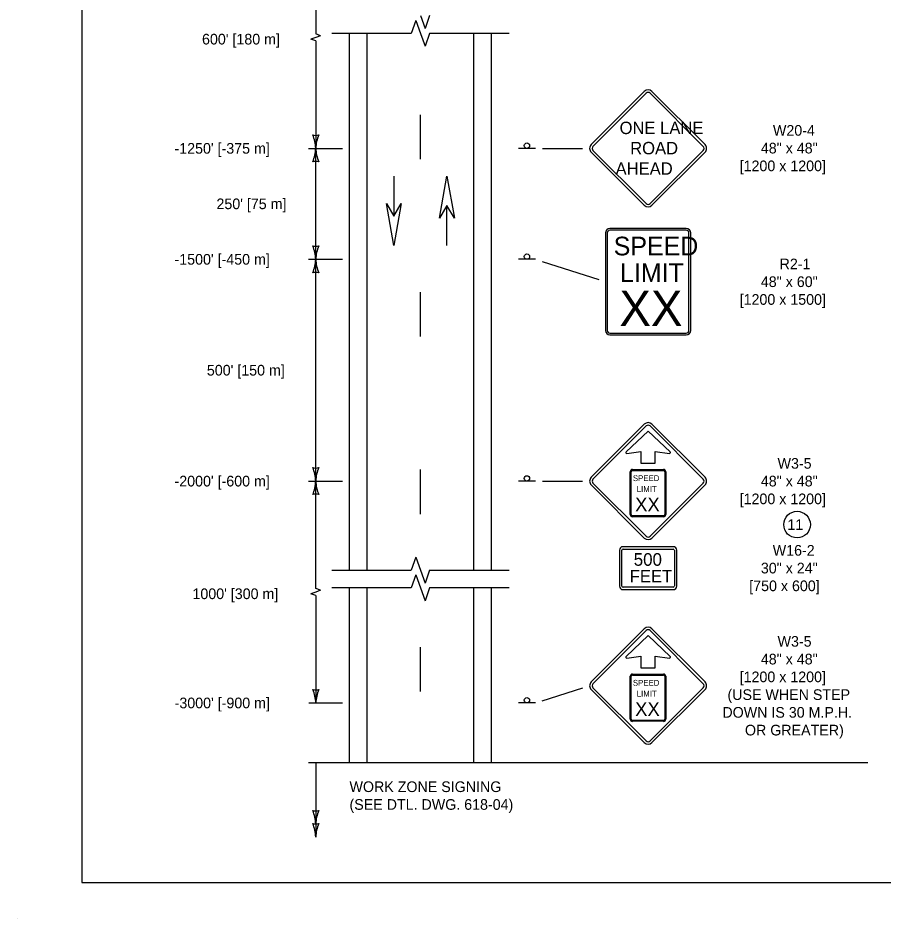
# Model space of a CAD drawing. Extents: x 49991.4 to 50021, y 49987.6 to 50011.4.
# Drawn here: x 49999.98 to 50004.85, y 49999.86 to 50004.93 of the extents above; entities that cross this region are included whole.
import ezdxf

# ---------------------------------------------------------------- set-up
doc = ezdxf.new("R2010")
doc.units = 0
for name, color, linetype in [('Level 1', 7, 'Continuous'), ('Level 2', 7, 'Continuous'), ('Level 3', 7, 'Continuous'), ('Level 6', 7, 'Continuous')]:
    doc.layers.add(name, color=color, linetype=linetype)

msp = doc.modelspace()

# ---------------------------------------------------------------- linework, layer by layer
at = {"layer": 'Level 1'}
for p, q in [((50001.8443, 50001.8221), (50001.8443, 50004.8471)), ((50001.9443, 50004.8119), (50001.9443, 50004.8482)), ((50001.9443, 50001.8221), (50001.9443, 50004.8471)), ((50002.5443, 50001.8221), (50002.5443, 50004.8471)), ((50002.6443, 50001.8221), (50002.6443, 50004.8471)), ((50003.5058, 50004.5198), (50003.2064, 50004.2205)), ((50003.5058, 50004.5198), (50003.5058, 50004.5198)), ((50003.848, 50004.2205), (50003.5486, 50004.5198)), ((50003.5159, 50004.5098), (50003.2165, 50004.2104)), ((50003.5159, 50004.5098), (50003.5159, 50004.5098)), ((50003.8379, 50004.2104), (50003.5385, 50004.5098)), ((50002.2443, 50004.1388), (50002.2443, 50004.3888)), ((50002.8923, 50004.1991), (50002.7963, 50004.1991)), ((50003.2064, 50004.1777), (50003.5058, 50003.8783)), ((50003.2165, 50004.1878), (50003.5159, 50003.8884)), ((50003.5385, 50003.8884), (50003.8379, 50004.1878)), ((50003.5486, 50003.8783), (50003.848, 50004.1777)), ((50002.094, 50004.0422), (50002.094, 50003.8163)), ((50002.0943, 50004.0422), (50002.0943, 50003.8163)), ((50002.3937, 50003.652), (50002.3937, 50003.8779)), ((50002.394, 50003.652), (50002.394, 50003.8779)), ((50003.2872, 50003.7227), (50003.2872, 50003.1727)), ((50003.2972, 50003.7227), (50003.2972, 50003.1727)), ((50003.7422, 50003.7477), (50003.3122, 50003.7477)), ((50003.7422, 50003.7377), (50003.3122, 50003.7377)), ((50003.7572, 50003.1727), (50003.7572, 50003.7227)), ((50003.7672, 50003.1727), (50003.7672, 50003.7227)), ((50002.8926, 50003.5738), (50002.7966, 50003.5738)), ((50002.2443, 50003.1388), (50002.2443, 50003.3888)), ((50003.3122, 50003.1577), (50003.7422, 50003.1577)), ((50003.3122, 50003.1477), (50003.7422, 50003.1477)), ((50003.5058, 50002.6448), (50003.2065, 50002.3455)), ((50003.5058, 50002.6448), (50003.5058, 50002.6448)), ((50003.8479, 50002.3455), (50003.5486, 50002.6448)), ((50003.5159, 50002.6347), (50003.2166, 50002.3354)), ((50003.5272, 50002.6063), (50003.4028, 50002.489)), ((50003.5159, 50002.6347), (50003.5159, 50002.6347)), ((50003.6516, 50002.489), (50003.5272, 50002.6063)), ((50003.8378, 50002.3354), (50003.5385, 50002.6347)), ((50003.4069, 50002.4804), (50003.4869, 50002.4904)), ((50003.4869, 50002.4904), (50003.4869, 50002.4249)), ((50003.5675, 50002.4249), (50003.5675, 50002.4904)), ((50003.5675, 50002.4904), (50003.6475, 50002.4804)), ((50003.4393, 50002.3898), (50003.6141, 50002.3898)), ((50003.4869, 50002.4249), (50003.5675, 50002.4249)), ((50003.5267, 50002.3898), (50003.5267, 50002.3898)), ((50002.2443, 50002.1388), (50002.2443, 50002.3888)), ((50003.4268, 50002.136), (50003.4268, 50002.3773)), ((50003.432, 50002.136), (50003.432, 50002.3773)), ((50003.4393, 50002.3846), (50003.6141, 50002.3846)), ((50003.6213, 50002.3773), (50003.6213, 50002.136)), ((50003.6265, 50002.3773), (50003.6265, 50002.136)), ((50002.8923, 50002.3241), (50002.7963, 50002.3241)), ((50003.2065, 50002.3027), (50003.5058, 50002.0034)), ((50003.2166, 50002.3128), (50003.5159, 50002.0135)), ((50003.5385, 50002.0135), (50003.8378, 50002.3128)), ((50003.5486, 50002.0034), (50003.8479, 50002.3027)), ((50003.6141, 50002.1288), (50003.4393, 50002.1288)), ((50003.6141, 50002.1236), (50003.4393, 50002.1236)), ((50003.3659, 50001.9344), (50003.3659, 50001.7328)), ((50003.3794, 50001.7328), (50003.3794, 50001.9344)), ((50003.6683, 50001.9546), (50003.3861, 50001.9546)), ((50003.3861, 50001.9411), (50003.6683, 50001.9411)), ((50003.6751, 50001.9344), (50003.6751, 50001.7328)), ((50003.6885, 50001.7328), (50003.6885, 50001.9344)), ((50001.8443, 50000.7385), (50001.8443, 50001.7221)), ((50001.9443, 50000.7385), (50001.9443, 50001.7221)), ((50002.5443, 50000.7385), (50002.5443, 50001.7221)), ((50002.6443, 50000.7385), (50002.6443, 50001.7221)), ((50003.6683, 50001.7261), (50003.3861, 50001.7261)), ((50003.3861, 50001.7126), (50003.6683, 50001.7126)), ((50003.5058, 50001.4918), (50003.2065, 50001.1925)), ((50003.5159, 50001.4817), (50003.2166, 50001.1824)), ((50003.5058, 50001.4918), (50003.5058, 50001.4918)), ((50003.5159, 50001.4817), (50003.5159, 50001.4817)), ((50003.8378, 50001.1824), (50003.5385, 50001.4817)), ((50003.8479, 50001.1925), (50003.5486, 50001.4918)), ((50003.5272, 50001.4533), (50003.4028, 50001.336)), ((50003.6516, 50001.336), (50003.5272, 50001.4533)), ((50002.2443, 50001.1388), (50002.2443, 50001.3888)), ((50003.4069, 50001.3274), (50003.4869, 50001.3374)), ((50003.4869, 50001.3374), (50003.4869, 50001.2719)), ((50003.5675, 50001.2719), (50003.5675, 50001.3374)), ((50003.5675, 50001.3374), (50003.6475, 50001.3274)), ((50003.4268, 50000.983), (50003.4268, 50001.2243)), ((50003.432, 50000.983), (50003.432, 50001.2243)), ((50003.4393, 50001.2368), (50003.6141, 50001.2368)), ((50003.4393, 50001.2316), (50003.6141, 50001.2316)), ((50003.4869, 50001.2719), (50003.5675, 50001.2719)), ((50003.5267, 50001.2368), (50003.5267, 50001.2368)), ((50003.6213, 50001.2243), (50003.6213, 50000.983)), ((50003.6265, 50001.2243), (50003.6265, 50000.983)), ((50003.2065, 50001.1497), (50003.5058, 50000.8504)), ((50003.2166, 50001.1598), (50003.5159, 50000.8605)), ((50003.5385, 50000.8605), (50003.8378, 50001.1598)), ((50003.5486, 50000.8504), (50003.8479, 50001.1497)), ((50002.8923, 50001.0741), (50002.7963, 50001.0741)), ((50003.6141, 50000.9758), (50003.4393, 50000.9758)), ((50003.6141, 50000.9706), (50003.4393, 50000.9706)), ((49999.9766, 49999.8624), (49999.9766, 49999.8624))]:
    msp.add_line(p, q, dxfattribs=at)
for points in [[(50008.6146, 50011.2628), (50000.3356, 50011.2628), (50000.3356, 50000.0624), (50008.6146, 50000.0624)], [(50002.352, 50003.8056), (50002.3937, 50004.0421), (50002.4356, 50003.8056), (50002.3937, 50003.8778)], [(50002.136, 50003.8886), (50002.0943, 50003.6521), (50002.0524, 50003.8886), (50002.0943, 50003.8164)]]:
    msp.add_lwpolyline(points, close=True, dxfattribs=at)
for centre in [(50002.8443, 50004.2144), (50002.8446, 50003.5891), (50002.8443, 50002.3394), (50002.8443, 50001.0893)]:
    msp.add_circle(centre, 0.0152, dxfattribs=at)
for centre, radius, start, end in [((50003.5272, 50004.4985), 0.0302, 45.0001, 134.9999), ((50003.5272, 50004.4985), 0.016, 45.0001, 134.9999), ((50003.2278, 50004.1991), 0.0302, 134.9999, 225.0001), ((50003.8266, 50004.1991), 0.0302, 314.9999, 45.0001), ((50003.2278, 50004.1991), 0.016, 134.9999, 225.0001), ((50003.8266, 50004.1991), 0.016, 314.9999, 45.0001), ((50003.5272, 50003.8997), 0.0302, 225.0001, 314.9999), ((50003.5272, 50003.8997), 0.016, 225.0001, 314.9999), ((50003.3122, 50003.7227), 0.025, 90, 180), ((50003.3122, 50003.7227), 0.015, 90, 180), ((50003.7422, 50003.7227), 0.025, 0, 90), ((50003.7422, 50003.7227), 0.015, 0, 90), ((50003.3122, 50003.1727), 0.025, 180, 270), ((50003.3122, 50003.1727), 0.015, 180, 270), ((50003.7422, 50003.1727), 0.025, 270, 0), ((50003.7422, 50003.1727), 0.015, 270, 0), ((50003.5272, 50002.6234), 0.0302, 45.0001, 134.9999), ((50003.5272, 50002.6234), 0.016, 45.0001, 134.9999), ((50003.4063, 50002.4854), 0.00508, 134.6287, 275.8295), ((50003.648, 50002.4854), 0.00509, 264.3826, 45.1649), ((50003.4393, 50002.3773), 0.0125, 90, 180), ((50003.6141, 50002.3773), 0.0125, 360, 90), ((50003.2279, 50002.3241), 0.0302, 134.9999, 225.0001), ((50003.4393, 50002.3773), 0.00728, 90, 180), ((50003.6141, 50002.3773), 0.00728, 360, 90), ((50003.8265, 50002.3241), 0.0302, 314.9999, 45.0001), ((50003.2279, 50002.3241), 0.016, 134.9999, 225.0001), ((50003.8265, 50002.3241), 0.016, 314.9999, 45.0001), ((50003.4393, 50002.136), 0.0125, 180, 270), ((50003.4393, 50002.136), 0.00728, 180, 270), ((50003.6141, 50002.136), 0.00728, 270, 360), ((50003.6141, 50002.136), 0.0125, 270, 360), ((50003.5272, 50002.0248), 0.0302, 225.0001, 314.9999), ((50003.5272, 50002.0248), 0.016, 225.0001, 314.9999), ((50003.3861, 50001.9344), 0.0202, 90, 180), ((50003.3861, 50001.9344), 0.00672, 90, 180), ((50003.6683, 50001.9344), 0.0202, 0, 90), ((50003.6683, 50001.9344), 0.00672, 0, 90), ((50003.3861, 50001.7328), 0.0202, 180, 270), ((50003.3861, 50001.7328), 0.00672, 180, 270), ((50003.6683, 50001.7328), 0.00672, 270, 360), ((50003.6683, 50001.7328), 0.0202, 270, 360), ((50003.5272, 50001.4704), 0.0302, 45.0001, 134.9999), ((50003.5272, 50001.4704), 0.016, 45.0001, 134.9999), ((50003.4063, 50001.3324), 0.00508, 134.6287, 275.8295), ((50003.648, 50001.3324), 0.00509, 264.3826, 45.1649), ((50003.4393, 50001.2243), 0.0125, 90, 180), ((50003.4393, 50001.2243), 0.00728, 90, 180), ((50003.6141, 50001.2243), 0.0125, 360, 90), ((50003.6141, 50001.2243), 0.00728, 360, 90), ((50003.2279, 50001.1711), 0.0302, 134.9999, 225.0001), ((50003.2279, 50001.1711), 0.016, 134.9999, 225.0001), ((50003.8265, 50001.1711), 0.016, 314.9999, 45.0001), ((50003.8265, 50001.1711), 0.0302, 314.9999, 45.0001), ((50003.4393, 50000.983), 0.0125, 180, 270), ((50003.4393, 50000.983), 0.00728, 180, 270), ((50003.6141, 50000.983), 0.00728, 270, 360), ((50003.6141, 50000.983), 0.0125, 270, 360), ((50003.5272, 50000.8718), 0.0302, 225.0001, 314.9999), ((50003.5272, 50000.8718), 0.016, 225.0001, 314.9999)]:
    msp.add_arc(centre, radius, start, end, dxfattribs=at)
at = {"layer": 'Level 2'}
msp.add_circle((50004.3665, 50002.0791), 0.075, dxfattribs=at)
at = {"layer": 'Level 3'}
for p, q in [((50001.6543, 50005.3709), (50001.6544, 50004.8435)), ((50001.6544, 50004.8241), (50001.627, 50004.8144)), ((50001.6818, 50004.8338), (50001.6544, 50004.8435)), ((50001.6818, 50004.8338), (50001.6544, 50004.8241)), ((50001.6541, 50004.8048), (50001.627, 50004.8144)), ((50001.6541, 50004.8048), (50001.6544, 50004.1991)), ((50001.6143, 50004.1991), (50001.8043, 50004.1991)), ((50001.6544, 50003.5738), (50001.6544, 50004.1991)), ((50002.9323, 50004.1991), (50003.1576, 50004.1991)), ((50001.6144, 50003.5738), (50001.8043, 50003.5738)), ((50001.6544, 50002.3241), (50001.6544, 50003.5738)), ((50002.9307, 50003.5616), (50003.2491, 50003.4599)), ((50001.6144, 50002.3241), (50001.8043, 50002.3241)), ((50001.6544, 50001.7185), (50001.6544, 50002.3241)), ((50002.9323, 50002.3241), (50003.1577, 50002.3241)), ((50001.6544, 50001.6991), (50001.627, 50001.6894)), ((50001.655, 50001.6795), (50001.627, 50001.6894)), ((50001.6818, 50001.7088), (50001.6544, 50001.7185)), ((50001.6818, 50001.7088), (50001.6544, 50001.6991)), ((50001.655, 50001.6795), (50001.655, 50001.0741)), ((50002.9304, 50001.0862), (50003.1595, 50001.159)), ((50001.615, 50001.0741), (50001.8043, 50001.0741)), ((50001.6143, 50000.7385), (50004.7645, 50000.7385)), ((50001.6544, 50000.7385), (50001.6544, 50000.3188))]:
    msp.add_line(p, q, dxfattribs=at)
for centre, radius, start, end in [((50001.6544, 50004.3273), 0.0548, 252.1388, 287.8612), ((50001.4217, 50004.1876), 0.233, 2.8273, 22.0772), ((50001.8765, 50004.1899), 0.2223, 157.456, 177.6395), ((50001.4323, 50004.2082), 0.2223, 337.456, 357.6395), ((50001.8871, 50004.2106), 0.233, 182.8273, 202.0772), ((50001.6544, 50004.0709), 0.0548, 72.1388, 107.8612), ((50001.6544, 50003.702), 0.0548, 252.1388, 287.8612), ((50001.4217, 50003.5623), 0.233, 2.8273, 22.0772), ((50001.8765, 50003.5647), 0.2223, 157.456, 177.6395), ((50001.4323, 50003.583), 0.2223, 337.456, 357.6395), ((50001.8871, 50003.5853), 0.233, 182.8273, 202.0772), ((50001.6544, 50003.4456), 0.0548, 72.1388, 107.8612), ((50001.6544, 50002.4523), 0.0548, 252.1388, 287.8612), ((50001.4217, 50002.3126), 0.233, 2.8273, 22.0772), ((50001.8765, 50002.3149), 0.2223, 157.456, 177.6395), ((50001.4323, 50002.3332), 0.2223, 337.456, 357.6395), ((50001.8871, 50002.3356), 0.233, 182.8273, 202.0772), ((50001.6544, 50002.1959), 0.0548, 72.1388, 107.8612), ((50001.655, 50001.2023), 0.0548, 252.1388, 287.8612), ((50001.4223, 50001.0626), 0.233, 2.8273, 22.0772), ((50001.8771, 50001.0649), 0.2223, 157.456, 177.6395), ((50001.6544, 50000.5205), 0.0548, 252.1388, 287.8612), ((50001.4217, 50000.3807), 0.233, 2.8273, 22.0772), ((50001.8765, 50000.3831), 0.2223, 157.456, 177.6395), ((50001.6544, 50000.447), 0.0548, 252.1388, 287.8612), ((50001.4217, 50000.3073), 0.233, 2.8273, 22.0772), ((50001.8765, 50000.3096), 0.2223, 157.456, 177.6395)]:
    msp.add_arc(centre, radius, start, end, dxfattribs=at)
at = {"layer": 'Level 6'}
for p, q in [((50002.2443, 50004.9471), (50002.2702, 50004.874)), ((50002.2961, 50004.9471), (50002.2702, 50004.874)), ((50002.2184, 50004.9202), (50002.1925, 50004.8471)), ((50002.2184, 50004.9202), (50002.2443, 50004.8471)), ((50002.1925, 50004.8471), (50001.7443, 50004.8471)), ((50002.2443, 50004.8471), (50002.2702, 50004.774)), ((50002.2961, 50004.8471), (50002.2702, 50004.774)), ((50002.7443, 50004.8471), (50002.2961, 50004.8471)), ((50002.2184, 50001.8952), (50002.1925, 50001.8221)), ((50002.2184, 50001.8952), (50002.2443, 50001.8221)), ((50001.7443, 50001.8221), (50002.1925, 50001.8221)), ((50002.2184, 50001.7952), (50002.1925, 50001.7221)), ((50002.2184, 50001.7952), (50002.2443, 50001.7221)), ((50002.2443, 50001.8221), (50002.2702, 50001.749)), ((50002.2961, 50001.8221), (50002.2702, 50001.749)), ((50002.2961, 50001.8221), (50002.7443, 50001.8221)), ((50002.1925, 50001.7221), (50001.7443, 50001.7221)), ((50002.2443, 50001.7221), (50002.2702, 50001.649)), ((50002.2961, 50001.7221), (50002.2702, 50001.649)), ((50002.7443, 50001.7221), (50002.2961, 50001.7221))]:
    msp.add_line(p, q, dxfattribs=at)

# ---------------------------------------------------------------- texts
at = {"layer": 'Level 1'}
for s, height, p in [('ONE LANE', 0.06989, (50003.3665, 50004.2796)), ('ROAD', 0.06989, (50003.4261, 50004.1655)), ('  AHEAD', 0.06989, (50003.292, 50004.0502)), ('SPEED', 0.10512, (50003.3334, 50003.5961)), ('LIMIT', 0.10512, (50003.3689, 50003.446)), ('XX', 0.19892, (50003.3657, 50003.1987)), ('500', 0.07124, (50003.4463, 50001.847)), ('FEET', 0.06989, (50003.4239, 50001.7529))]:
    msp.add_text(s, height=height, dxfattribs=at).set_placement(p)
for s, height, p in [('SPEED', 0.03301, (50003.4414, 50002.3241)), ('LIMIT', 0.03301, (50003.4632, 50002.2631)), ('XX', 0.07775, (50003.4542, 50002.1537)), ('SPEED', 0.03301, (50003.4414, 50001.1711)), ('LIMIT', 0.03301, (50003.4632, 50001.1101)), ('XX', 0.07775, (50003.4542, 50001.0007))]:
    msp.add_text(s, height=height, rotation=360, dxfattribs=at).set_placement(p)
at = {"layer": 'Level 2'}
for s, p in [("600' [180 m]", (50001.0136, 50004.7844)), ('W20-4', (50004.2307, 50004.2704)), ("-1250' [-375 m]", (50000.8585, 50004.1691)), ('48" x 48"', (50004.1627, 50004.1704)), ('[1200 x 1200]', (50004.0432, 50004.0704)), ("250' [75 m]", (50001.0949, 50003.8565)), ("-1500' [-450 m]", (50000.8586, 50003.5438)), ('R2-1', (50004.2682, 50003.5177)), ('48" x 60"', (50004.1627, 50003.4177)), ('[1200 x 1500]', (50004.0432, 50003.3177)), ("500' [150 m]", (50001.041, 50002.919)), ('W3-5', (50004.2567, 50002.3941)), ("-2000' [-600 m]", (50000.8586, 50002.2941)), ('48" x 48"', (50004.1627, 50002.2941)), ('[1200 x 1200]', (50004.0432, 50002.1941)), ('11', (50004.3121, 50002.0491)), ('W16-2', (50004.2295, 50001.9041)), ('30" x 24"', (50004.1627, 50001.8041)), ('[750 x 600]', (50004.0971, 50001.7041)), ("1000' [300 m]", (50000.9597, 50001.6594)), ('W3-5', (50004.2567, 50001.3911)), ('48" x 48"', (50004.1627, 50001.2911)), ('[1200 x 1200]', (50004.0432, 50001.1911)), ('(USE WHEN STEP', (50003.9746, 50001.0911)), ("-3000' [-900 m]", (50000.8592, 50001.0441)), ('DOWN IS 30 M.P.H.', (50003.9457, 50000.9911)), ('OR GREATER)', (50004.0729, 50000.8911)), ('WORK ZONE SIGNING', (50001.8446, 50000.5721)), ('(SEE DTL. DWG. 618-04)', (50001.8446, 50000.4721))]:
    msp.add_text(s, height=0.06, dxfattribs=at).set_placement(p)

doc.saveas('drawing.dxf')
